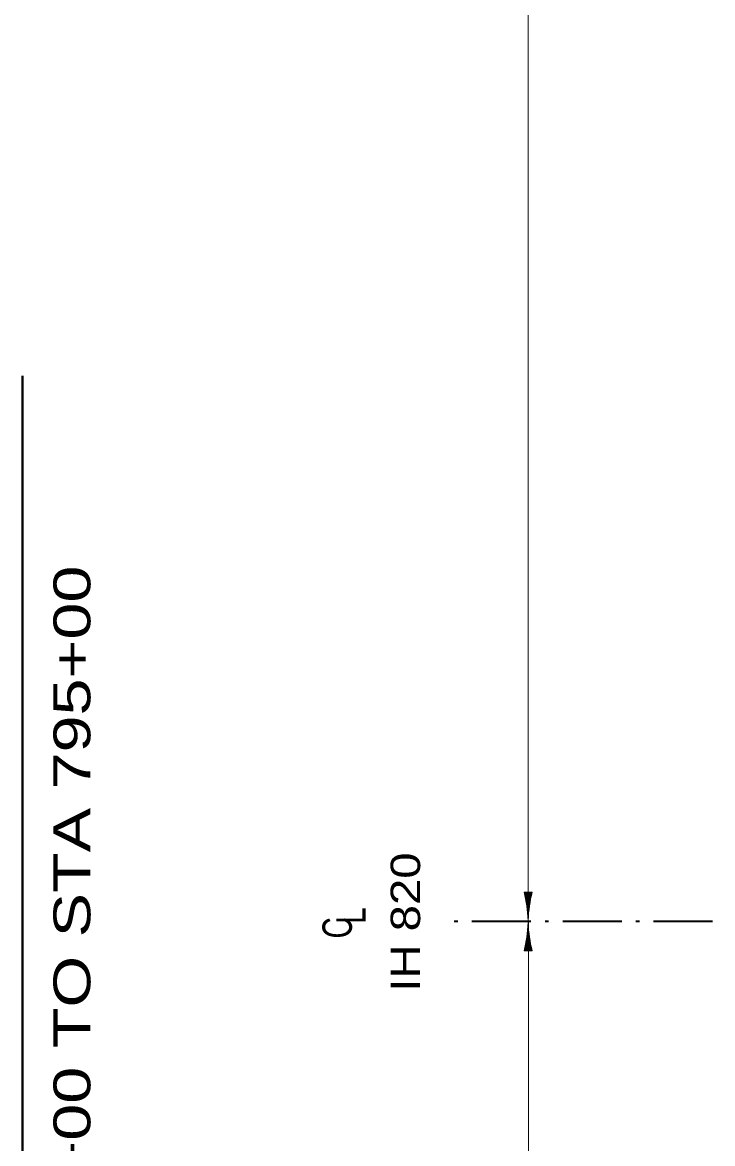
# Model space of a CAD drawing. Extents: x 2363427 to 2368559, y 6957299 to 6980140.
# Drawn here: x 2364471 to 2364799, y 6961278 to 6961811 of the extents above; entities that cross this region are included whole.
import ezdxf
from ezdxf.enums import TextEntityAlignment as Align

# ---------------------------------------------------------------- set-up
doc = ezdxf.new("R2010")
doc.units = 0
doc.header["$LTSCALE"] = 5.6
doc.linetypes.add('DOT_DASHED', pattern=[7.7, 5, -1.2, 0.3, -1.2])
doc.layers.add('4', color=7, linetype='Continuous', lineweight=13)

msp = doc.modelspace()

# ---------------------------------------------------------------- linework, layer by layer
at = {"layer": '4'}
for p, q in [((2364711.601, 6961383.064), (2364711.601, 6962455.938)), ((2364709.685, 6961397.78), (2364713.515, 6961397.78)), ((2364710.035, 6961397.78), (2364710.035, 6961396.196)), ((2364710.535, 6961397.78), (2364710.535, 6961393.504)), ((2364711.035, 6961397.78), (2364711.035, 6961390.43)), ((2364711.535, 6961397.78), (2364711.535, 6961385.216)), ((2364712.035, 6961397.78), (2364712.035, 6961389.171)), ((2364712.535, 6961397.78), (2364712.535, 6961392.918)), ((2364713.035, 6961397.78), (2364713.035, 6961395.399)), ((2364711.535, 6961369.776), (2364711.535, 6961382.34)), ((2364711.737, 6960333.27), (2364711.737, 6961383.778)), ((2364711.035, 6961369.776), (2364711.035, 6961377.126)), ((2364712.035, 6961369.776), (2364712.035, 6961378.385)), ((2364709.685, 6961369.776), (2364713.515, 6961369.776)), ((2364710.035, 6961369.776), (2364710.035, 6961371.36)), ((2364710.535, 6961369.776), (2364710.535, 6961374.052)), ((2364712.535, 6961369.776), (2364712.535, 6961374.638)), ((2364713.035, 6961369.776), (2364713.035, 6961372.157))]:
    msp.add_line(p, q, dxfattribs=at)
at = {"layer": '4', "lineweight": 40}
msp.add_line((2364471.469, 6961048.18), (2364471.469, 6961642.941), dxfattribs=at)
at = {"layer": '4', "linetype": 'DOT_DASHED', "lineweight": 35}
msp.add_line((2364799.192, 6961383.778), (2364671.949, 6961383.778), dxfattribs=at)
at = {"layer": '4'}
for centre, start, end in [((2364639.477, 6961380.887), 2.84356, 13.52961), ((2364783.724, 6961380.887), 166.47039, 177.15644), ((2364639.477, 6961386.67), 346.47039, 357.15644), ((2364783.724, 6961386.67), 182.84356, 193.52961)]:
    msp.add_arc(centre, 72.212, start, end, dxfattribs=at)

# ---------------------------------------------------------------- texts
for s, height, width, p in [('STA 786+00 TO STA 795+00', 17.5, 1.35, (2364503.722, 6961345.542)), ('IH 820', 14, 1.2, (2364660.335, 6961383.486)), ('L', 14, 0.75, (2364634.459, 6961386.536)), ('C', 14, 0.75, (2364627.927, 6961380.775))]:
    msp.add_text(s, height=height, rotation=90, dxfattribs=dict(at, width=width)).set_placement(p, align=Align.CENTER)

doc.saveas('drawing.dxf')
